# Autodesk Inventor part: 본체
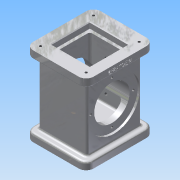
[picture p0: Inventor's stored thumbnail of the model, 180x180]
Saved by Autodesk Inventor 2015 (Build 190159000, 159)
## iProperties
Created: 2017-08
Part Number: 본체
Material: 알루미늄 6061
Document SubType Name: Modeling
Designer: Administrator
Density: 2.7 g/cm^3
Appearance: 알루미늄 - 평지
Mass: 1004.01 g
Surface Area: 664.104 cm^2
Volume: 371.855 cm^3
Author: Administrator
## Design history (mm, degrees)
sketch "스케치1"
  geometry: L1 (41, -46)-(-41, -46); L2 (-41, -46)-(-41, 46); L3 (-41, 46)-(41, 46); L4 (41, 46)-(41, -46); L5 (41, -46)-(-41, 46); L6 (-41, -46)-(41, 46); 1 further point
  constraints: 12 end point, 2 midpoint, 2 parallel, 1 horizontal, 1 perpendicular
  dimensions: "d0" = 82 distance between parallel lines of L2 L4; "d2" = 92 distance between parallel lines of L3 L1
extrude "돌출1" new body sketch "스케치1" distance "d3" = 10; taper "d4" = 0 deg
sketch "스케치2"
  geometry: L1 (-33, 37)-(33, 37); L2 (33, 37)-(33, -37); L3 (33, -37)-(-33, -37); L4 (-33, -37)-(-33, 37); L5 (-33, 37)-(33, -37); L6 (33, 37)-(-33, -37); 1 further point
  constraints: 12 end point, 2 midpoint, 2 parallel, 1 horizontal, 1 perpendicular
  dimensions: "d5" = 66 distance between parallel lines of L2 L4; "d6" = 74 distance between parallel lines of L3 L1
extrude "돌출2" join sketch "스케치2" distance "d7" = 88; taper "d8" = 0 deg
sketch "스케치6"
  geometry: L1 (-24, 24)-(24, 24); L2 (24, 24)-(24, -24); L3 (24, -24)-(-24, -24); L4 (-24, -24)-(-24, 24); L5 (-24, 24)-(24, -24); L6 (24, 24)-(-24, -24); 1 further point
  constraints: 12 end point, 2 midpoint, 2 parallel, 1 horizontal, 1 perpendicular
  dimensions: "d21" = 48 distance between parallel lines of L2 L4; "d22" = 48 distance between parallel lines of L3 L1
extrude "돌출6" cut sketch "스케치6" distance "d23" = 16; taper "d24" = 0 deg
sketch "스케치7"
  geometry: C1 r 35 at (37, 44); 1 further point
  constraints: 1 centre point, 1 vertical alignment
  dimensions: "d28" = 70 diameter of C1; "d29" = 54 distance of point (37, -10) C1.centre
extrude "돌출7" cut sketch "스케치7" distance "d30" = 3; taper "d31" = 0 deg
sketch "스케치8"
  geometry: C1 r 35 at (0, 0) reference; C2 r 24 at (0, 0); 1 further point
  constraints: 1 centre point, 1 coincident
  dimensions: "d32" = 48 diameter of C2
extrude "돌출8" cut sketch "스케치8" stored distance "d33" = 3; taper "d34" = 0 deg
sketch "스케치9"
  geometry: C1 r 24 at (0, 0) reference; 2 further points
  constraints: 1 vertical alignment
  dimensions: "d35" = 29 distance of C1.centre point (0, 29)
hole "구멍1" sketch "스케치9" at (0, 29) diameter "d36" = 3.242; stored, may be unused: countersink angle "d40" = 90 deg, drill point angle "d42" = 118 deg; dims "d37" = 4, "d38" = 4, "d39" = 2, "d41" = 6
fillet "모깎기2" dims "d60" = 10
sketch "스케치14"
  geometry: L1 (-41, -46)-(41, -46); L2 (41, -46)-(41, 46); L3 (41, 46)-(-41, 46); L4 (-41, 46)-(-41, -46); L5 (-41, -46)-(41, 46); L6 (41, -46)-(-41, 46); 1 further point
  constraints: 12 end point, 2 midpoint, 2 parallel, 1 horizontal, 1 perpendicular
  dimensions: "d77" = 92 distance between parallel lines of L3 L1; "d78" = 82 distance between parallel lines of L2 L4
extrude "돌출9" join sketch "스케치14" distance "d79" = 10; taper "d80" = 0 deg
sketch "스케치15"
  geometry: L1 (-26, 26)-(26, 26); L2 (26, 26)-(26, -26); L3 (26, -26)-(-26, -26); L4 (-26, -26)-(-26, 26); L5 (-26, 26)-(26, -26); L6 (26, 26)-(-26, -26); 1 further point
  constraints: 12 end point, 2 midpoint, 2 parallel, 1 horizontal, 1 perpendicular
  dimensions: "d81" = 52 distance between parallel lines of L4 L2; "d82" = 52 distance between parallel lines of L3 L1
extrude "돌출10" cut sketch "스케치15" distance "d83" = 8; taper "d84" = 0 deg
sketch "스케치16"
  geometry: L1 (-22, 22)-(22, 22); L2 (22, 22)-(22, -22); L3 (22, -22)-(-22, -22); L4 (-22, -22)-(-22, 22); L5 (-22, 22)-(22, -22); L6 (22, 22)-(-22, -22); 1 further point
  constraints: 12 end point, 2 midpoint, 2 parallel, 1 horizontal, 1 perpendicular
  dimensions: "d85" = 44 distance between parallel lines of L4 L2; "d86" = 44 distance between parallel lines of L3 L1
extrude "돌출11" cut sketch "스케치16" distance "d87" = 74; taper "d88" = 0 deg
fillet "모깎기3" dims "d89" = 10
sketch "스케치17"
  geometry: A1 r 10 centre (31, 36) between (41, 36) and (31, 46) reference; 2 further points
  constraints: 1 coincident
hole "구멍4" sketch "스케치17" at (31, 36) diameter "d90" = 3.242; stored, may be unused: countersink angle "d94" = 90 deg, drill point angle "d96" = 118 deg; dims "d91" = 4, "d92" = 4, "d93" = 2, "d95" = 6
node "작업 평면2"
sketch "스케치18"
  geometry: L1 (0, 0)-(72, 0) reference; L2 (0, 10)-(-10, 10) reference; L3 (-10, 10)-(-10, 0) reference; L4 (-10, 0)-(0, 0) reference; L5 (0, 0)-(0, 10) reference; 2 further points
  constraints: 1 other
  dimensions: "d103" = 46 distance from line of L3 point (36, 4); "d104" = 4 distance from line of L1 point (36, 4)
feature "엠보싱2" sketch "스케치18" dims "d21" = 48, "d22" = 48, "d105" = 0.5, "d106" = 0
fillet "모깎기4" dims "d107" = 3
fillet "모깎기5" dims "d108" = 3
fillet "모깎기6" dims "d109" = 3
fillet "모깎기7" dims "d110" = 3
fillet "모깎기9" dims "d112" = 3
fillet "모깎기10" dims "d113" = 3
fillet "모깎기11" dims "d114" = 3
sketch "스케치19"
  geometry: L1 (61, -95)-(-1, -95) reference; 4 further points
  constraints: 2 vertical alignment, 1 midpoint
  dimensions: "d115" = 38 distance from line of L1 point (30, -57); "d116" = 42 distance of point (30, -57) point (30, -15)
hole "구멍5" sketch "스케치19" at (30, -57), (30, -15) diameter "d117" = 4.134; stored, may be unused: countersink angle "d121" = 90 deg, drill point angle "d123" = 0 deg; dims "d118" = 10, "d119" = 4, "d120" = 2, "d122" = 50
chamfer "모따기1" distance "d124" = 1; stored, may be unused: second distance "d125" = 2, angle "d126" = 45 deg
fillet "모깎기12" dims "d127" = 1
fillet "모깎기13" dims "d128" = 3
fillet "모깎기14" dims "d129" = 3
node "솔리드1"
mirror "대칭1"
pattern_circular "원형 패턴1" dims angle "d44" = 360 deg
mirror "대칭2"
pattern_linear "직사각형 패턴2" dims "d99" = 72, "d102" = 62
mirror "대칭4"
node "투영된 루프3"
